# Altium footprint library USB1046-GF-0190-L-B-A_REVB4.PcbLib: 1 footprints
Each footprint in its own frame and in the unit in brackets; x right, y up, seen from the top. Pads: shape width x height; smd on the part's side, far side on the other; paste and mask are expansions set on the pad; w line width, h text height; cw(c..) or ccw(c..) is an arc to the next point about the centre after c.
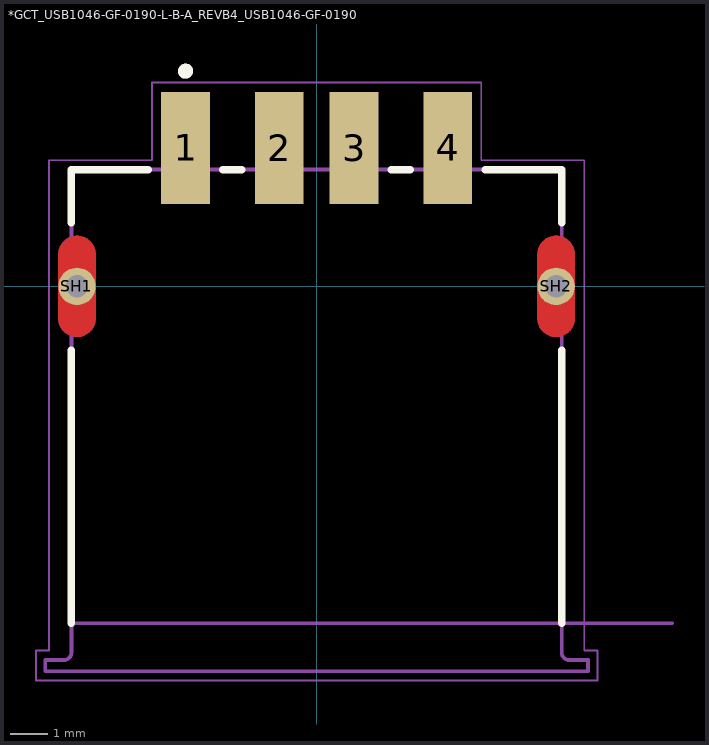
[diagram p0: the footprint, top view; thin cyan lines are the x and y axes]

## *GCT_USB1046-GF-0190-L-B-A_REVB4_USB1046-GF-0190-L-B-A_REVB4(Primary) [mm]
pads (6):
  rect 1.3x3 smd: 1(-3.5,3.7) 2(-1,3.7) 3(1,3.7) 4(3.5,3.7)
  round 1 hole 0.6: SH1(-6.4,0) SH2(6.4,0)
Top Layer:
  region: 6.9,0.85 6.9,-0.85 6.899,-0.876 6.897,-0.902 6.894,-0.928 6.889,-0.954 6.883,-0.979 6.876,-1.005 6.867,-1.029 6.857,-1.053 6.846,-1.077 6.833,-1.1 6.819,-1.122 6.805,-1.144 6.789,-1.165 6.772,-1.185 6.754,-1.204 6.735,-1.222 6.715,-1.239 6.694,-1.255 6.672,-1.269 6.65,-1.283 6.627,-1.295 6.603,-1.307 6.579,-1.317 6.555,-1.326 6.529,-1.333 6.504,-1.339 6.478,-1.344 6.452,-1.347 6.426,-1.349 6.4,-1.35 6.374,-1.349 6.348,-1.347 6.322,-1.344 6.296,-1.339 6.271,-1.333 6.245,-1.326 6.221,-1.317 6.197,-1.307 6.173,-1.295 6.15,-1.283 6.128,-1.269 6.106,-1.255 6.085,-1.239 6.065,-1.222 6.046,-1.204 6.028,-1.185 6.011,-1.165 5.995,-1.144 5.981,-1.122 5.967,-1.1 5.954,-1.077 5.943,-1.053 5.933,-1.029 5.924,-1.005 5.917,-0.979 5.911,-0.954 5.906,-0.928 5.903,-0.902 5.901,-0.876 5.9,-0.85 5.9,0.85 5.901,0.876 5.903,0.902 5.906,0.928 5.911,0.954 5.917,0.979 5.924,1.005 5.933,1.029 5.943,1.053 5.954,1.077 5.967,1.1 5.981,1.122 5.995,1.144 6.011,1.165 6.028,1.185 6.046,1.204 6.065,1.222 6.085,1.239 6.106,1.255 6.128,1.269 6.15,1.283 6.173,1.295 6.197,1.307 6.221,1.317 6.245,1.326 6.271,1.333 6.296,1.339 6.322,1.344 6.348,1.347 6.374,1.349 6.4,1.35 6.426,1.349 6.452,1.347 6.478,1.344 6.504,1.339 6.529,1.333 6.555,1.326 6.579,1.317 6.603,1.307 6.627,1.295 6.65,1.283 6.672,1.269 6.694,1.255 6.715,1.239 6.735,1.222 6.754,1.204 6.772,1.185 6.789,1.165 6.805,1.144 6.819,1.122 6.833,1.1 6.846,1.077 6.857,1.053 6.867,1.029 6.876,1.005 6.883,0.979 6.889,0.954 6.894,0.928 6.897,0.902 6.899,0.876
  region: -5.9,0.85 -5.9,-0.85 -5.901,-0.876 -5.903,-0.902 -5.906,-0.928 -5.911,-0.954 -5.917,-0.979 -5.924,-1.005 -5.933,-1.029 -5.943,-1.053 -5.954,-1.077 -5.967,-1.1 -5.981,-1.122 -5.995,-1.144 -6.011,-1.165 -6.028,-1.185 -6.046,-1.204 -6.065,-1.222 -6.085,-1.239 -6.106,-1.255 -6.128,-1.269 -6.15,-1.283 -6.173,-1.295 -6.197,-1.307 -6.221,-1.317 -6.245,-1.326 -6.271,-1.333 -6.296,-1.339 -6.322,-1.344 -6.348,-1.347 -6.374,-1.349 -6.4,-1.35 -6.426,-1.349 -6.452,-1.347 -6.478,-1.344 -6.504,-1.339 -6.529,-1.333 -6.555,-1.326 -6.579,-1.317 -6.603,-1.307 -6.627,-1.295 -6.65,-1.283 -6.672,-1.269 -6.694,-1.255 -6.715,-1.239 -6.735,-1.222 -6.754,-1.204 -6.772,-1.185 -6.789,-1.165 -6.805,-1.144 -6.819,-1.122 -6.833,-1.1 -6.846,-1.077 -6.857,-1.053 -6.867,-1.029 -6.876,-1.005 -6.883,-0.979 -6.889,-0.954 -6.894,-0.928 -6.897,-0.902 -6.899,-0.876 -6.9,-0.85 -6.9,0.85 -6.899,0.876 -6.897,0.902 -6.894,0.928 -6.889,0.954 -6.883,0.979 -6.876,1.005 -6.867,1.029 -6.857,1.053 -6.846,1.077 -6.833,1.1 -6.819,1.122 -6.805,1.144 -6.789,1.165 -6.772,1.185 -6.754,1.204 -6.735,1.222 -6.715,1.239 -6.694,1.255 -6.672,1.269 -6.65,1.283 -6.627,1.295 -6.603,1.307 -6.579,1.317 -6.555,1.326 -6.529,1.333 -6.504,1.339 -6.478,1.344 -6.452,1.347 -6.426,1.349 -6.4,1.35 -6.374,1.349 -6.348,1.347 -6.322,1.344 -6.296,1.339 -6.271,1.333 -6.245,1.326 -6.221,1.317 -6.197,1.307 -6.173,1.295 -6.15,1.283 -6.128,1.269 -6.106,1.255 -6.085,1.239 -6.065,1.222 -6.046,1.204 -6.028,1.185 -6.011,1.165 -5.995,1.144 -5.981,1.122 -5.967,1.1 -5.954,1.077 -5.943,1.053 -5.933,1.029 -5.924,1.005 -5.917,0.979 -5.911,0.954 -5.906,0.928 -5.903,0.902 -5.901,0.876
Bottom Layer:
  region: 5.9,0.85 5.9,-0.85 5.901,-0.876 5.903,-0.902 5.906,-0.928 5.911,-0.954 5.917,-0.979 5.924,-1.005 5.933,-1.029 5.943,-1.053 5.954,-1.077 5.967,-1.1 5.981,-1.122 5.995,-1.144 6.011,-1.165 6.028,-1.185 6.046,-1.204 6.065,-1.222 6.085,-1.239 6.106,-1.255 6.128,-1.269 6.15,-1.283 6.173,-1.295 6.197,-1.307 6.221,-1.317 6.245,-1.326 6.271,-1.333 6.296,-1.339 6.322,-1.344 6.348,-1.347 6.374,-1.349 6.4,-1.35 6.426,-1.349 6.452,-1.347 6.478,-1.344 6.504,-1.339 6.529,-1.333 6.555,-1.326 6.579,-1.317 6.603,-1.307 6.627,-1.295 6.65,-1.283 6.672,-1.269 6.694,-1.255 6.715,-1.239 6.735,-1.222 6.754,-1.204 6.772,-1.185 6.789,-1.165 6.805,-1.144 6.819,-1.122 6.833,-1.1 6.846,-1.077 6.857,-1.053 6.867,-1.029 6.876,-1.005 6.883,-0.979 6.889,-0.954 6.894,-0.928 6.897,-0.902 6.899,-0.876 6.9,-0.85 6.9,0.85 6.899,0.876 6.897,0.902 6.894,0.928 6.889,0.954 6.883,0.979 6.876,1.005 6.867,1.029 6.857,1.053 6.846,1.077 6.833,1.1 6.819,1.122 6.805,1.144 6.789,1.165 6.772,1.185 6.754,1.204 6.735,1.222 6.715,1.239 6.694,1.255 6.672,1.269 6.65,1.283 6.627,1.295 6.603,1.307 6.579,1.317 6.555,1.326 6.529,1.333 6.504,1.339 6.478,1.344 6.452,1.347 6.426,1.349 6.4,1.35 6.374,1.349 6.348,1.347 6.322,1.344 6.296,1.339 6.271,1.333 6.245,1.326 6.221,1.317 6.197,1.307 6.173,1.295 6.15,1.283 6.128,1.269 6.106,1.255 6.085,1.239 6.065,1.222 6.046,1.204 6.028,1.185 6.011,1.165 5.995,1.144 5.981,1.122 5.967,1.1 5.954,1.077 5.943,1.053 5.933,1.029 5.924,1.005 5.917,0.979 5.911,0.954 5.906,0.928 5.903,0.902 5.901,0.876
  region: -6.9,0.85 -6.9,-0.85 -6.899,-0.876 -6.897,-0.902 -6.894,-0.928 -6.889,-0.954 -6.883,-0.979 -6.876,-1.005 -6.867,-1.029 -6.857,-1.053 -6.846,-1.077 -6.833,-1.1 -6.819,-1.122 -6.805,-1.144 -6.789,-1.165 -6.772,-1.185 -6.754,-1.204 -6.735,-1.222 -6.715,-1.239 -6.694,-1.255 -6.672,-1.269 -6.65,-1.283 -6.627,-1.295 -6.603,-1.307 -6.579,-1.317 -6.555,-1.326 -6.529,-1.333 -6.504,-1.339 -6.478,-1.344 -6.452,-1.347 -6.426,-1.349 -6.4,-1.35 -6.374,-1.349 -6.348,-1.347 -6.322,-1.344 -6.296,-1.339 -6.271,-1.333 -6.245,-1.326 -6.221,-1.317 -6.197,-1.307 -6.173,-1.295 -6.15,-1.283 -6.128,-1.269 -6.106,-1.255 -6.085,-1.239 -6.065,-1.222 -6.046,-1.204 -6.028,-1.185 -6.011,-1.165 -5.995,-1.144 -5.981,-1.122 -5.967,-1.1 -5.954,-1.077 -5.943,-1.053 -5.933,-1.029 -5.924,-1.005 -5.917,-0.979 -5.911,-0.954 -5.906,-0.928 -5.903,-0.902 -5.901,-0.876 -5.9,-0.85 -5.9,0.85 -5.901,0.876 -5.903,0.902 -5.906,0.928 -5.911,0.954 -5.917,0.979 -5.924,1.005 -5.933,1.029 -5.943,1.053 -5.954,1.077 -5.967,1.1 -5.981,1.122 -5.995,1.144 -6.011,1.165 -6.028,1.185 -6.046,1.204 -6.065,1.222 -6.085,1.239 -6.106,1.255 -6.128,1.269 -6.15,1.283 -6.173,1.295 -6.197,1.307 -6.221,1.317 -6.245,1.326 -6.271,1.333 -6.296,1.339 -6.322,1.344 -6.348,1.347 -6.374,1.349 -6.4,1.35 -6.426,1.349 -6.452,1.347 -6.478,1.344 -6.504,1.339 -6.529,1.333 -6.555,1.326 -6.579,1.317 -6.603,1.307 -6.627,1.295 -6.65,1.283 -6.672,1.269 -6.694,1.255 -6.715,1.239 -6.735,1.222 -6.754,1.204 -6.772,1.185 -6.789,1.165 -6.805,1.144 -6.819,1.122 -6.833,1.1 -6.846,1.077 -6.857,1.053 -6.867,1.029 -6.876,1.005 -6.883,0.979 -6.889,0.954 -6.894,0.928 -6.897,0.902 -6.899,0.876
Top Overlay:
  circle w0.2: c-3.5,5.75 r0.1
  lines w0.2: -6.55,-9 -6.55,-1.7 ; -6.55,1.7 -6.55,3.12 -4.5,3.12 ; -2.5,3.12 -2,3.12 ; 2,3.12 2.5,3.12 ; 4.5,3.12 6.55,3.12 6.55,1.7 ; 6.55,-9 6.55,-1.7
Top Solder:
  drawing of 2 lines, arcs and shapes, not listed
Bottom Solder:
  drawing of 2 lines, arcs and shapes, not listed
Mechanical 1:
  lines w0: -6.7,-0.85 ccw(c-6.4,-0.85) -6.4,-1.15 ccw(c-6.4,-0.85) -6.1,-0.85 -6.1,0.85 ccw(c-6.4,0.85) -6.4,1.15 ccw(c-6.4,0.85) -6.7,0.85 -6.7,-0.85 ; 6.1,-0.85 ccw(c6.4,-0.85) 6.4,-1.15 ccw(c6.4,-0.85) 6.7,-0.85 6.7,0.85 ccw(c6.4,0.85) 6.4,1.15 ccw(c6.4,0.85) 6.1,0.85 6.1,-0.85
Mechanical 4:
  circle w0.2: c-3.5,5.75 r0.1
  circle w0.2: c-3.5,5.75 r0.1
  lines w0.1: -7.25,-10.28 7.25,-10.28 ; -7.25,-10.28 -7.25,-9.98 ; -7.25,-10.28 7.25,-10.28 ; -7.25,-10.28 -7.25,-9.98 ; -7.25,-9.98 -6.75,-9.98 ; -7.25,-9.98 -6.75,-9.98 ; -6.75,-9.98 ccw(c-6.75,-9.78) -6.55,-9.78 ; -6.75,-9.98 ccw(c-6.75,-9.78) -6.55,-9.78 ; -6.55,-9.78 -6.55,-9 ; -6.55,-9.78 -6.55,-9 ; -6.55,-9 9.5,-9 -6.55,-9 ; -6.55,-9 -6.55,3.12 ; -6.55,-9 -6.55,3.12 ; -6.55,3.12 6.55,3.12 ; -6.55,3.12 6.55,3.12 ; 6.55,-9.78 ccw(c6.75,-9.78) 6.75,-9.98 ; 6.55,-9.78 ccw(c6.75,-9.78) 6.75,-9.98 ; 6.55,-9.78 6.55,3.12 ; 6.55,-9.78 6.55,3.12 ; 6.75,-9.98 7.25,-9.98 ; 6.75,-9.98 7.25,-9.98 ; 7.25,-10.28 7.25,-9.98 ; 7.25,-10.28 7.25,-9.98
  text "PCB EDGE" at 7.25,-9 h1.88
  text "PCB EDGE" at 7.25,-9 h1.88
Mechanical 16:
  lines w0.05: -7.5,-10.53 -7.5,-9.73 -7.15,-9.73 -7.15,3.37 -4.4,3.37 -4.4,5.45 4.4,5.45 4.4,3.37 7.15,3.37 7.15,-9.73 7.5,-9.73 7.5,-10.53 -7.5,-10.53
